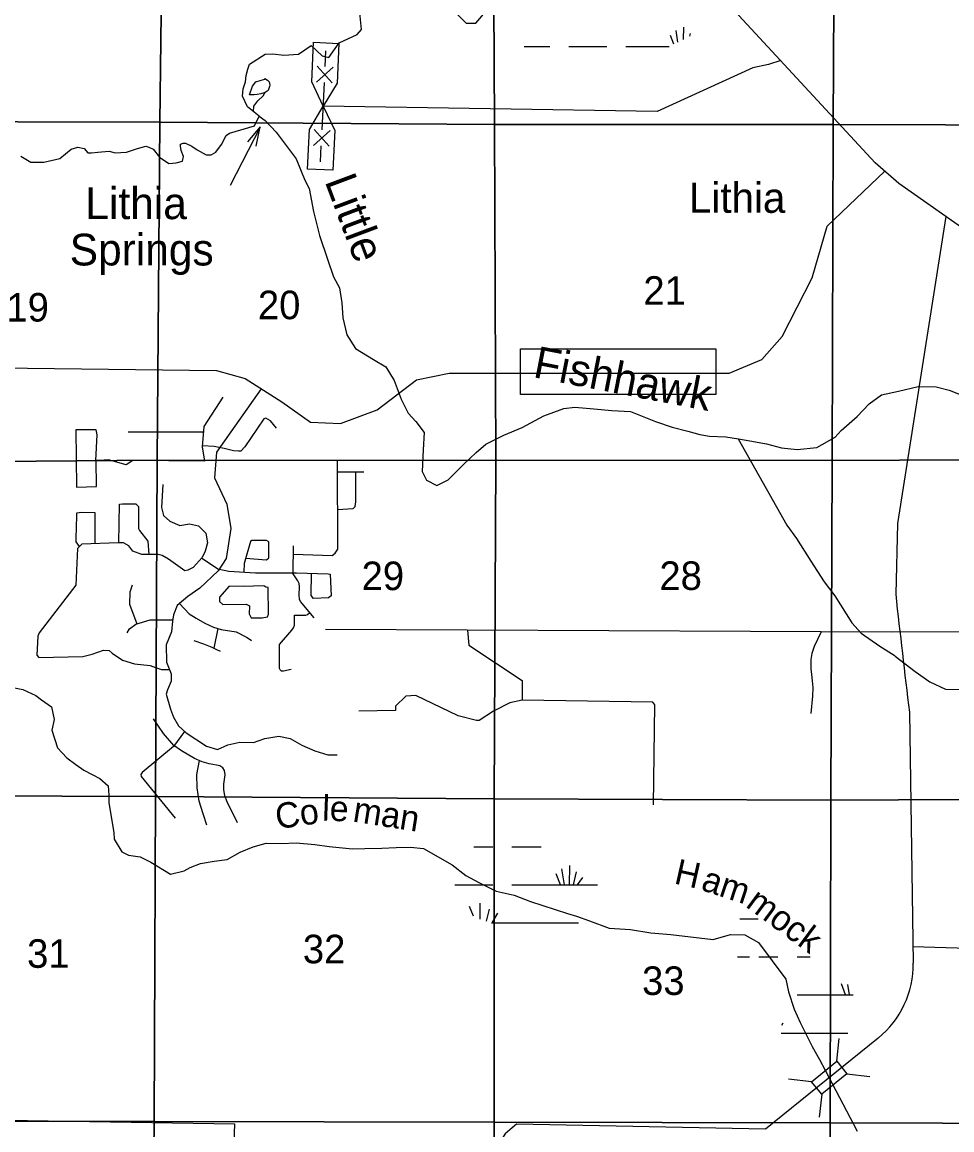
# Model space of a CAD drawing. Extents: x 380424 to 701066, y 1117407 to 1412949.
# Drawn here: x 577750 to 592389, y 1267730 to 1285181 of the extents above; entities that cross this region are included whole.
import ezdxf

# ---------------------------------------------------------------- set-up
doc = ezdxf.new("R2010")
doc.units = 0
for name, color, linetype in [('Bridges', 7, 'Continuous'), ('Bridges and Drawbridges Local Roads', 7, 'Continuous'), ('Communities and Subdivisions Names without Post Office', 7, 'Continuous'), ('County Routes Highway Center Lines', 7, 'Continuous'), ('Islands Text Inland (Hammocks and Ridges etc)', 7, 'Continuous'), ('Lakes and Ponds', 7, 'Continuous'), ('Lakes and Ponds Text', 7, 'Continuous'), ('Local Roads Paved', 7, 'Continuous'), ('Local Roads Related Cells', 7, 'Continuous'), ('Masks for Text', 7, 'Continuous'), ('Narrow River Creek and Branch and Slough', 7, 'Continuous'), ('Narrow River Creek and Branch and Slough Text', 7, 'Continuous'), ('Section Lines', 7, 'Continuous'), ('Section Numbers', 7, 'Continuous'), ('Swamps', 7, 'Continuous'), ('Township  and Range lines', 7, 'Continuous'), ('Wide Rivers and Canals Text', 7, 'Continuous')]:
    doc.layers.add(name, color=color, linetype=linetype)

msp = doc.modelspace()

# ---------------------------------------------------------------- linework, layer by layer
at = {"layer": 'Bridges'}
msp.add_line((590738, 1268611), (591098, 1268573), dxfattribs=at)
at = {"layer": 'Bridges and Drawbridges Local Roads'}
for p, q in [((590577, 1268811), (590616, 1269171)), ((590179, 1268489), (589819, 1268527)), ((590340, 1268290), (590301, 1267930))]:
    msp.add_line(p, q, dxfattribs=at)
msp.add_lwpolyline([(590738, 1268611), (590340, 1268290), (590179, 1268489), (590577, 1268811)], close=True, dxfattribs=at)
at = {"layer": 'County Routes Highway Center Lines'}
msp.add_lwpolyline([(596897, 1278886), (591554, 1282639), (591181, 1282965), (587604, 1286841)], dxfattribs=at)
at = {"layer": 'Lakes and Ponds'}
msp.add_lwpolyline([(581375, 1284174), (581427, 1284243), (581496, 1284264), (581570, 1284285), (581570, 1284291), (581612, 1284269), (581638, 1284243), (581649, 1284190), (581644, 1284169), (581623, 1284106), (581575, 1284074), (581507, 1284053), (581448, 1284043), (581401, 1284037), (581332, 1284037)], close=True, dxfattribs=at)
at = {"layer": 'Local Roads Paved'}
for p, q in [((580603, 1278724), (579420, 1278724)), ((582714, 1278099), (583131, 1278094)), ((582017, 1276503), (582022, 1276930)), ((580774, 1275318), (580835, 1275628)), ((591721, 1274311), (591781, 1270357))]:
    msp.add_line(p, q, dxfattribs=at)
for points in [[(589695, 1284576), (589500, 1284515), (589257, 1284463), (587748, 1283771), (582491, 1283856)], [(554030, 1279561), (569039, 1279549), (570781, 1279523), (571489, 1279801), (571874, 1279801), (580810, 1279694), (581261, 1279565), (581839, 1279201), (582289, 1278879), (582761, 1278858), (583339, 1279072), (583961, 1279544), (584475, 1279651), (586714, 1279651), (588881, 1279651), (589395, 1279866), (589716, 1280230), (590188, 1281152), (590424, 1281967), (591334, 1282831)], [(592292, 1282120), (591531, 1277281), (591505, 1276168)], [(581514, 1279406), (580812, 1278409), (580779, 1278002), (580973, 1277587), (581037, 1277203), (580963, 1276730), (580835, 1276537), (580546, 1276263), (580358, 1276134), (580192, 1275989), (580133, 1275845), (580117, 1275743), (580101, 1275577), (580015, 1275373), (580021, 1275100), (580096, 1274912), (580096, 1274801), (580037, 1274661), (580015, 1274592), (580085, 1274356), (580133, 1274233), (580214, 1274093), (580331, 1273986), (580653, 1273777), (580824, 1273723), (580990, 1273798), (581178, 1273836), (581392, 1273831), (581573, 1273895), (581793, 1273932), (581970, 1273895), (582152, 1273793), (582361, 1273702), (582564, 1273638), (582709, 1273638)], [(580909, 1279271), (580609, 1278810), (580587, 1278488), (580620, 1278263), (579495, 1278274), (579388, 1278209), (579109, 1278284), (578970, 1278274), (578911, 1278276), (578932, 1278678), (578916, 1278759), (578846, 1278759), (578595, 1278759), (578605, 1277853), (578922, 1277863), (578916, 1278276)], [(581754, 1278784), (581658, 1278902), (581588, 1278940), (581556, 1278934), (581256, 1278489), (581192, 1278420), (581154, 1278420), (581079, 1278430), (580929, 1278463), (580774, 1278495), (580589, 1278505)], [(591777, 1270617), (599795, 1270377), (599775, 1274156), (599831, 1278498)], [(582021, 1276797), (582633, 1276780), (582681, 1276813), (582719, 1276877), (582713, 1278265)], [(582716, 1277503), (582960, 1277520), (582992, 1277552), (583003, 1277622), (583003, 1278095)], [(579966, 1277896), (579945, 1277536), (579977, 1277408), (580073, 1277322), (580234, 1277252), (580384, 1277279), (580529, 1277247), (580641, 1277129), (580668, 1276979), (580631, 1276845), (580582, 1276748), (580443, 1276587), (580357, 1276550), (580309, 1276539), (580052, 1276721), (579955, 1276780), (579891, 1276796), (579634, 1276796), (579495, 1276845), (579430, 1276931), (579345, 1276979), (579264, 1276979), (578691, 1276957), (578622, 1276888), (578595, 1276309), (578017, 1275559), (577996, 1275506), (577980, 1275206), (578012, 1275174), (578708, 1275190), (578853, 1275222), (579030, 1275286), (579121, 1275281), (579169, 1275238), (579330, 1275131), (579517, 1275072), (579764, 1275046), (579849, 1275013), (579946, 1274981), (580068, 1274981)], [(579271, 1276979), (579282, 1277586), (579330, 1277591), (579539, 1277591), (579565, 1277564), (579581, 1277548), (579581, 1277205), (579597, 1277173), (579731, 1277002), (579743, 1276796)], [(578654, 1276920), (578601, 1276996), (578601, 1277044), (578612, 1277404), (578612, 1277452), (578687, 1277463), (578896, 1277457), (578896, 1276965)], [(581269, 1276734), (581595, 1276712), (581632, 1276744), (581632, 1276953), (581632, 1276996), (581600, 1277017), (581364, 1277017), (581343, 1277001), (581247, 1276653), (581241, 1276518)], [(580576, 1276741), (580829, 1276571), (581005, 1276530), (581423, 1276508), (582072, 1276503), (582570, 1276492), (582602, 1276487), (582618, 1276144), (582575, 1276112), (582339, 1276101), (582302, 1276149), (582307, 1276498)], [(582347, 1275796), (582132, 1276055), (582117, 1276088), (582111, 1276155), (582115, 1276292), (582113, 1276339), (582093, 1276380), (582005, 1276504)], [(579480, 1276310), (579447, 1276203), (579442, 1276010), (579555, 1275704)], [(581230, 1276289), (581011, 1276294), (580855, 1276122), (580855, 1276053), (580909, 1276004), (581279, 1276010), (581332, 1275988), (581327, 1275860), (581354, 1275795), (581530, 1275795), (581611, 1275811), (581627, 1275854), (581622, 1276273), (581589, 1276278), (581557, 1276299), (581230, 1276289)], [(580230, 1276022), (580379, 1275857), (580491, 1275792), (580625, 1275712), (580764, 1275648), (580882, 1275615), (581118, 1275578), (581295, 1275487), (581359, 1275438)], [(581984, 1274982), (581864, 1274954), (581834, 1274956), (581813, 1274976), (581803, 1274997), (581803, 1275025), (581801, 1275378), (581998, 1275601), (582020, 1275640), (582036, 1275682), (582040, 1275749), (582036, 1275836), (582215, 1275840), (582245, 1275850), (582278, 1275879)], [(579405, 1275560), (579442, 1275624), (579539, 1275699), (579764, 1275764), (579924, 1275764), (580120, 1275764)], [(601609, 1275610), (591450, 1275572), (582525, 1275615)], [(584760, 1275604), (584786, 1275368), (585621, 1274811), (585621, 1274499), (585429, 1274457), (585171, 1274328), (584946, 1274178), (584903, 1274178), (584614, 1274253), (583950, 1274575), (583789, 1274564), (583629, 1274403), (583629, 1274339), (583050, 1274328)], [(590330, 1275577), (590222, 1275344), (590185, 1275237), (590171, 1275140), (590167, 1274995), (590178, 1274905), (590191, 1274805), (590198, 1274698), (590195, 1274560), (590167, 1274290)], [(580454, 1275438), (580604, 1275385), (580738, 1275336), (580802, 1275304), (580866, 1275272)], [(587689, 1272849), (587711, 1274424), (587679, 1274467), (585621, 1274499)], [(581140, 1272569), (580976, 1272897), (580941, 1272994), (580927, 1273092), (580927, 1273176), (580945, 1273322), (580936, 1273393), (580910, 1273433), (580865, 1273464), (580808, 1273477), (580697, 1273495), (580586, 1273530), (580462, 1273583), (580258, 1273703), (580139, 1273783), (579975, 1273973), (579820, 1274204)], [(580308, 1274007), (580134, 1273770), (579638, 1273362), (579621, 1273326), (579625, 1273295), (580161, 1272639)], [(580657, 1272529), (580600, 1272710), (580538, 1272910), (580507, 1273118), (580502, 1273331), (580542, 1273549)], [(591227, 1269175), (589454, 1267742), (585534, 1267821), (585467, 1267761), (585357, 1267668), (584686, 1266632), (584593, 1266496), (584482, 1266445), (581046, 1266473)], [(577179, 1267886), (581092, 1267827), (580994, 1264949)]]:
    msp.add_lwpolyline(points, dxfattribs=at)
for centre, radius, start, end in [((759241, 1294764), 168764, 186.32633, 186.96116), ((590290, 1270335), 1491, 308.947, 0.8636)]:
    msp.add_arc(centre, radius, start, end, dxfattribs=at)
at = {"layer": 'Local Roads Related Cells'}
for p, q in [((582309, 1284240), (582339, 1284865)), ((582339, 1284865), (582739, 1284845)), ((582521, 1284480), (582533, 1284730)), ((582739, 1284845), (582708, 1284221)), ((582384, 1284237), (582646, 1284474)), ((582396, 1284486), (582634, 1284225)), ((582491, 1283856), (582309, 1284240)), ((582472, 1283482), (582509, 1284231)), ((582708, 1284221), (582491, 1283856)), ((582273, 1283491), (582491, 1283856)), ((582491, 1283856), (582672, 1283472)), ((582243, 1282867), (582273, 1283491)), ((582348, 1283488), (582585, 1283226)), ((582338, 1283238), (582600, 1283475)), ((582672, 1283472), (582642, 1282848)), ((582448, 1282982), (582460, 1283232)), ((582642, 1282848), (582243, 1282867))]:
    msp.add_line(p, q, dxfattribs=at)
at = {"layer": 'Masks for Text'}
msp.add_lwpolyline([(585596, 1280033), (588672, 1280033), (588672, 1279315), (585596, 1279315)], close=True, dxfattribs=at)
at = {"layer": 'Narrow River Creek and Branch and Slough'}
for points in [[(584572, 1285332), (584739, 1285166), (584892, 1285166), (585110, 1285415)], [(577727, 1283071), (577884, 1282973), (578089, 1282973), (578344, 1283032), (578520, 1283179), (578628, 1283209), (578726, 1283189), (578785, 1283120), (578843, 1283120), (578941, 1283130), (579118, 1283150), (579216, 1283120), (579392, 1283130), (579568, 1283189), (579695, 1283228), (579744, 1283209), (579813, 1283179), (579911, 1283052), (580058, 1282954), (580175, 1282964), (580273, 1282993), (580293, 1283062), (580254, 1283160), (580244, 1283228), (580244, 1283258), (580283, 1283277), (580322, 1283277), (580420, 1283228), (580508, 1283169), (580645, 1283091), (580724, 1283091), (580802, 1283130), (580890, 1283253), (580964, 1283393), (581016, 1283430), (581406, 1283550), (581480, 1283702), (581298, 1283845), (581220, 1284015), (581230, 1284130), (581267, 1284241), (581278, 1284342), (581303, 1284439), (581331, 1284517), (581575, 1284678), (581695, 1284683), (581870, 1284660), (582100, 1284674), (582302, 1284812), (582473, 1284650), (582578, 1284623), (582740, 1284853), (583025, 1284987), (583094, 1285065), (583066, 1285328)], [(581392, 1283771), (581399, 1283855), (581461, 1283940), (581545, 1284022), (581579, 1284077)], [(581480, 1283702), (581578, 1283633), (581752, 1283449), (582063, 1283026), (582200, 1282694), (582271, 1282558), (582338, 1282198), (582433, 1281818), (582559, 1281449), (582654, 1281169), (582749, 1280995), (582786, 1280758), (582797, 1280525), (582865, 1280256), (582997, 1280040), (583282, 1279866), (583477, 1279750), (583609, 1279533), (583720, 1279243), (583826, 1279022), (583947, 1278890), (584079, 1278716), (584063, 1278441), (584047, 1278103), (584116, 1277966), (584279, 1277882), (584459, 1277972), (584701, 1278214), (584897, 1278399), (585050, 1278531), (585335, 1278673), (585625, 1278795), (585963, 1278979), (586279, 1279095), (586453, 1279117), (586754, 1279090), (587034, 1279064), (587329, 1279048), (587725, 1278890), (587983, 1278800), (588231, 1278737), (588421, 1278684), (588574, 1278658), (588828, 1278647), (589028, 1278615), (589208, 1278584), (589471, 1278536), (589709, 1278473), (589952, 1278447), (590263, 1278478), (590553, 1278642), (590648, 1278747), (590896, 1278969), (591086, 1279169), (591281, 1279312), (591550, 1279370), (591860, 1279440), (592143, 1279434), (592349, 1279381), (592597, 1279281)], [(589022, 1278616), (589790, 1277255), (589943, 1277044), (590170, 1276690), (590381, 1276363), (590545, 1276142), (590812, 1275720), (590962, 1275556), (591257, 1275350), (591479, 1275208), (591498, 1275192), (591811, 1274949), (592043, 1274786), (592291, 1274675), (592560, 1274669)], [(577575, 1274706), (577760, 1274669), (577966, 1274574), (578055, 1274506), (578214, 1274395), (578256, 1274194), (578219, 1274026), (578309, 1273751), (578451, 1273593), (578594, 1273487), (578720, 1273398), (578852, 1273329), (578974, 1273266), (579105, 1273150), (579116, 1273002), (579116, 1272881), (579195, 1272416), (579200, 1272311), (579322, 1272110), (579422, 1272058), (579607, 1272031), (579776, 1271947), (580087, 1271757), (580303, 1271810), (580398, 1271862), (580556, 1271926), (580773, 1271963), (580979, 1271989), (581184, 1272105), (581385, 1272189), (581591, 1272247), (581828, 1272242), (582066, 1272253), (582356, 1272226), (582583, 1272195), (582952, 1272158), (583147, 1272163), (583416, 1272168), (583638, 1272179), (583865, 1272184), (584071, 1272163), (584519, 1271905), (584735, 1271736), (584941, 1271625), (585216, 1271488), (585495, 1271430), (585754, 1271329), (586339, 1271139), (586477, 1271097), (586682, 1271023), (586994, 1270907), (587331, 1270886), (587648, 1270833), (587965, 1270807), (588629, 1270728), (588904, 1270807), (589131, 1270802), (589347, 1270680), (589774, 1270105), (589817, 1269905), (589906, 1269630), (590001, 1269419), (590191, 1269045), (590307, 1268839), (590396, 1268669), (590899, 1267709)]]:
    msp.add_lwpolyline(points, dxfattribs=at)
at = {"layer": 'Section Lines'}
for points in [[(579946, 1288874), (579963, 1287452), (579916, 1283606), (575439, 1283616), (574493, 1283628), (574520, 1287465), (574513, 1288848), (574518, 1288848), (575452, 1288856)], [(585164, 1288874), (585166, 1287442), (585188, 1283568), (579916, 1283606), (579963, 1287452), (579946, 1288874)], [(590534, 1288877), (590539, 1287430), (590521, 1283566), (585188, 1283568), (585166, 1287442), (585164, 1288874)], [(595860, 1288832), (595851, 1287426), (595823, 1283554), (590521, 1283566), (590539, 1287430), (590534, 1288877)], [(579916, 1283606), (579878, 1278282), (575431, 1278244), (574467, 1278248), (574493, 1283628), (575439, 1283616)], [(585188, 1283568), (585211, 1278276), (585206, 1278276), (579878, 1278282), (579916, 1283606)], [(590521, 1283566), (590504, 1278276), (590502, 1278279), (585211, 1278276), (585188, 1283568)], [(595823, 1283554), (595793, 1278299), (590504, 1278276), (590521, 1283566)], [(579878, 1278282), (579849, 1272980), (575425, 1272995), (574466, 1273005), (574467, 1278248), (575431, 1278244)], [(585211, 1278276), (585184, 1272946), (579849, 1272980), (579878, 1278282), (585206, 1278276)], [(590504, 1278276), (590486, 1272923), (585184, 1272946), (585211, 1278276), (590502, 1278279)], [(595793, 1278299), (595804, 1272952), (590486, 1272923), (590504, 1278276)], [(579849, 1272980), (579831, 1267862), (575415, 1267874), (574445, 1267880), (574466, 1273005), (575425, 1272995)], [(585184, 1272946), (585183, 1267853), (579831, 1267862), (579849, 1272980)], [(590486, 1272923), (590472, 1267843), (585183, 1267853), (585184, 1272946)], [(595804, 1272952), (595787, 1267823), (590472, 1267843), (590486, 1272923)], [(579831, 1267862), (579772, 1262552), (575404, 1262462), (574395, 1262454), (574445, 1267880), (575415, 1267874)], [(585183, 1267853), (585124, 1262491), (579772, 1262552), (579831, 1267862)], [(590472, 1267843), (590419, 1262461), (585124, 1262491), (585183, 1267853)], [(595787, 1267823), (595786, 1262431), (590419, 1262461), (590472, 1267843)]]:
    msp.add_lwpolyline(points, close=True, dxfattribs=at)
at = {"layer": 'Swamps'}
for p, q in [((586357, 1284797), (586957, 1284797)), ((587257, 1284797), (587857, 1284797)), ((584861, 1272190), (585161, 1272190)), ((586289, 1271590), (586249, 1271844)), ((586367, 1271590), (586373, 1271894)), ((586434, 1271590), (586477, 1271796)), ((586226, 1271591), (586160, 1271764)), ((586496, 1271590), (586580, 1271704)), ((584561, 1271590), (585161, 1271590)), ((585461, 1271590), (586061, 1271590)), ((586061, 1271590), (586811, 1271590)), ((585237, 1271144), (585148, 1270990)), ((586061, 1270990), (586511, 1270990)), ((589051, 1271056), (589337, 1271056)), ((589351, 1270456), (589651, 1270456)), ((589951, 1270456), (590157, 1270456)), ((590716, 1269857), (590650, 1270029)), ((590779, 1269856), (590753, 1270018)), ((589951, 1269856), (590551, 1269856))]:
    msp.add_line(p, q, dxfattribs=at)
for points in [[(588165, 1284910), (588169, 1285101)], [(588010, 1284833), (587957, 1284971)], [(588075, 1284865), (588046, 1285051)], [(588264, 1284960), (588273, 1285003)], [(585654, 1284797), (586057, 1284797)], [(587857, 1284797), (587938, 1284797)], [(585461, 1272190), (585924, 1272190)], [(584959, 1271301), (584959, 1271048)], [(584790, 1271253), (584850, 1271100)], [(585104, 1271205), (585057, 1271016)], [(585142, 1270990), (586061, 1270990)], [(589014, 1270456), (589201, 1270456)], [(590551, 1269856), (590837, 1269856)], [(589727, 1269409), (589708, 1269376)], [(589703, 1269256), (590551, 1269256)], [(590551, 1269256), (590751, 1269256)]]:
    msp.add_lwpolyline(points, dxfattribs=at)
at = {"layer": 'Township  and Range lines'}
for p, q in [((575415, 1267874), (579831, 1267862)), ((579831, 1267862), (585183, 1267853)), ((585183, 1267853), (590472, 1267843)), ((590472, 1267843), (595787, 1267823))]:
    msp.add_line(p, q, dxfattribs=at)
at = {"layer": 'Wide Rivers and Canals Text'}
for p, q in [((581498, 1283531), (581298, 1283295)), ((581433, 1283228), (581498, 1283531))]:
    msp.add_line(p, q, dxfattribs=at)
msp.add_lwpolyline([(581498, 1283526), (581027, 1282608)], dxfattribs=at)

# ---------------------------------------------------------------- texts
at = {"layer": 'Communities and Subdivisions Names without Post Office'}
msp.add_text('Lithia', height=475, rotation=0.0004, dxfattribs=at).set_placement((588249, 1282177))
at = {"layer": 'Islands Text Inland (Hammocks and Ridges etc)'}
for s, rotation, p in [('le', 357.8594, (582469, 1272603)), ('Co', 8.3443, (581766, 1272465)), ('man', 350.9746, (582943, 1272589)), ('H', 347.3581, (588001, 1271614)), ('am', 341.6728, (588422, 1271515)), ('mock', 323.4712, (589127, 1271255))]:
    msp.add_text(s, height=400, rotation=rotation, dxfattribs=at).set_placement(p)
at = {"layer": 'Lakes and Ponds Text'}
for s, rotation, p in [('Little', 290.5644, (582509, 1282677)), ('Fishhawk', 349.0512, (585780, 1279590))]:
    msp.add_text(s, height=500, rotation=rotation, dxfattribs=at).set_placement(p)
at = {"layer": 'Narrow River Creek and Branch and Slough Text'}
for s, p in [('Lithia', (578745, 1282078)), ('Springs', (578499, 1281348))]:
    msp.add_text(s, height=500, rotation=0.0004, dxfattribs=at).set_placement(p)
at = {"layer": 'Section Numbers'}
for s, p in [('21', (587532, 1280728)), ('19', (577502, 1280464)), ('20', (581462, 1280501)), ('29', (583095, 1276233)), ('28', (587784, 1276236)), ('32', (582170, 1270354)), ('31', (577828, 1270283)), ('33', (587511, 1269855))]:
    msp.add_text(s, height=450, dxfattribs=at).set_placement(p)

doc.saveas('drawing.dxf')
